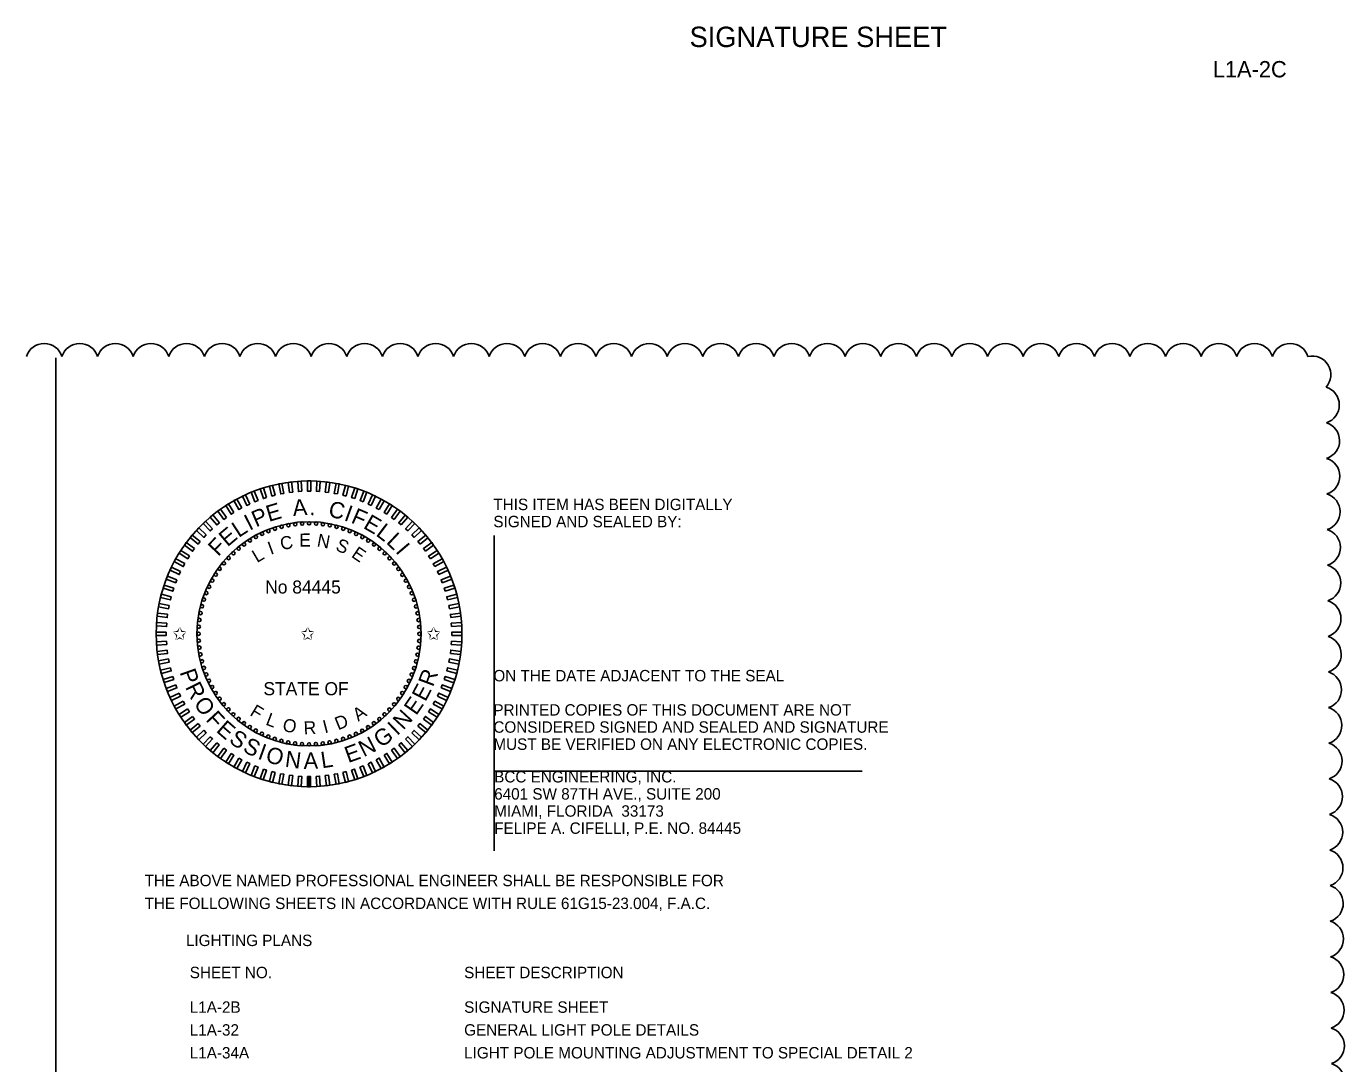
# Model space of a CAD drawing. Extents: x -811.2 to -795.1, y -2238.2 to -2204.
# Drawn here: x -803.27 to -795.18, y -2232.26 to -2225.9 of the extents above; entities that cross this region are included whole.
import ezdxf

# ---------------------------------------------------------------- set-up
doc = ezdxf.new("R2010")
doc.units = 0
for name, color, linetype in [('AdhocPoint_dp', 7, 'Continuous'), ('Cloud_dp', 7, 'Continuous'), ('PlotBorder_dp', 7, 'Continuous'), ('SheetLines_dp', 7, 'Continuous'), ('TextMinor', 7, 'Continuous'), ('TextMisc', 7, 'Continuous'), ('TextNotes', 7, 'Continuous'), ('TextShtNo', 7, 'Continuous')]:
    doc.layers.add(name, color=color, linetype=linetype)

msp = doc.modelspace()

# ---------------------------------------------------------------- linework, layer by layer
at = {"layer": 'AdhocPoint_dp'}
for p, q in [((-800.3974, -2229.0197), (-800.3974, -2230.9544)), ((-800.3974, -2230.4644), (-798.1407, -2230.4644))]:
    msp.add_line(p, q, dxfattribs=at)
at = {"layer": 'Cloud_dp'}
for centre, start, end in [((-803.1571, -2227.9569), 17.50004, 162.50004), ((-802.9388, -2227.9569), 17.5, 162.5), ((-802.7205, -2227.9569), 17.5, 162.5), ((-802.5022, -2227.9569), 17.5, 162.5), ((-802.2839, -2227.9569), 17.5, 162.5), ((-802.0655, -2227.9569), 17.5, 162.5), ((-801.8472, -2227.9569), 17.5, 162.5), ((-801.6289, -2227.9569), 17.5, 162.5), ((-801.4106, -2227.9569), 17.5, 162.5), ((-801.1922, -2227.9569), 17.5, 162.5), ((-800.9739, -2227.9569), 17.5, 162.5), ((-800.7556, -2227.9569), 17.5, 162.5), ((-800.5373, -2227.9569), 17.5, 162.5), ((-800.3189, -2227.9569), 17.5, 162.5), ((-800.1006, -2227.9569), 17.5, 162.5), ((-799.8823, -2227.9569), 17.5, 162.5), ((-799.664, -2227.9569), 17.5, 162.5), ((-799.4456, -2227.9569), 17.5, 162.5), ((-799.2273, -2227.9569), 17.5, 162.5), ((-799.009, -2227.9569), 17.5, 162.5), ((-798.7907, -2227.9569), 17.5, 162.5), ((-798.5724, -2227.9569), 17.5, 162.5), ((-798.354, -2227.9569), 17.5, 162.5), ((-798.1357, -2227.9569), 17.5, 162.5), ((-797.9174, -2227.9569), 17.5, 162.5), ((-797.6991, -2227.9569), 17.5, 162.5), ((-797.4807, -2227.9569), 17.5, 162.5), ((-797.2624, -2227.9569), 17.5, 162.5), ((-797.0441, -2227.9569), 17.5, 162.5), ((-796.8258, -2227.9569), 17.5, 162.5), ((-796.6074, -2227.9569), 17.5, 162.5), ((-796.3891, -2227.9569), 17.5, 162.5), ((-796.1708, -2227.9569), 17.5, 162.5), ((-795.9525, -2227.9569), 17.5, 162.5), ((-795.7341, -2227.9569), 17.5, 162.5), ((-795.5158, -2227.9569), 17.5, 162.5), ((-795.3807, -2228.034), 318.11161, 103.11161), ((-795.329, -2228.2198), 287.95289, 72.95289), ((-795.3273, -2228.4382), 287.95289, 72.95289), ((-795.3256, -2228.6565), 287.95289, 72.95289), ((-795.3239, -2228.8748), 287.95289, 72.95289), ((-795.3221, -2229.0931), 287.95289, 72.95289), ((-795.3204, -2229.3114), 287.95289, 72.95289), ((-795.3187, -2229.5297), 287.95289, 72.95289), ((-795.317, -2229.7481), 287.95289, 72.95289), ((-795.3152, -2229.9664), 287.95289, 72.95289), ((-795.3135, -2230.1847), 287.95289, 72.95289), ((-795.3118, -2230.403), 287.95289, 72.95289), ((-795.3101, -2230.6213), 287.95289, 72.95289), ((-795.3083, -2230.8396), 287.95289, 72.95289), ((-795.3066, -2231.058), 287.95289, 72.95289), ((-795.3049, -2231.2763), 287.95289, 72.95289), ((-795.3032, -2231.4946), 287.95289, 72.95289), ((-795.3014, -2231.7129), 287.95289, 72.95289), ((-795.2997, -2231.9312), 287.95289, 72.95289), ((-795.298, -2232.1495), 287.95289, 72.95289), ((-795.2963, -2232.3679), 287.95289, 72.95289)]:
    msp.add_arc(centre, 0.1145, start, end, dxfattribs=at)
at = {"layer": 'TextMinor'}
for radius in [0.9375, 0.6875]:
    msp.add_circle((-801.5329, -2229.6231), radius, dxfattribs=at)
at = {"layer": 'TextNotes'}
msp.add_line((-803.0858, -2237.5311), (-803.0858, -2227.9311), dxfattribs=at)
at = {"layer": 'TextShtNo'}
for p, q in [((-801.5429, -2230.5606), (-801.5431, -2230.4981)), ((-801.5329, -2230.5606), (-801.5331, -2230.4981)), ((-801.5229, -2230.5605), (-801.5231, -2230.498))]:
    msp.add_line(p, q, dxfattribs=at)
for points in [[(-801.7936, -2228.7877), (-801.8128, -2228.794), (-801.8321, -2228.7346), (-801.8129, -2228.7283)], [(-801.7407, -2228.773), (-801.7602, -2228.778), (-801.7757, -2228.7175), (-801.7562, -2228.7125)], [(-801.6869, -2228.7616), (-801.7067, -2228.7654), (-801.7184, -2228.7041), (-801.6986, -2228.7003)], [(-801.6325, -2228.7537), (-801.6525, -2228.7562), (-801.6603, -2228.6942), (-801.6403, -2228.6917)], [(-801.5777, -2228.7491), (-801.5978, -2228.7504), (-801.6018, -2228.6881), (-801.5816, -2228.6868)], [(-801.5227, -2228.748), (-801.5429, -2228.748), (-801.5429, -2228.6856), (-801.5227, -2228.6856)], [(-801.4678, -2228.7504), (-801.488, -2228.7491), (-801.484, -2228.6868), (-801.4639, -2228.6881)], [(-801.4131, -2228.7562), (-801.4332, -2228.7537), (-801.4253, -2228.6917), (-801.4053, -2228.6943)], [(-801.359, -2228.7655), (-801.3788, -2228.7617), (-801.3671, -2228.7003), (-801.3473, -2228.7041)], [(-801.3054, -2228.7781), (-801.325, -2228.773), (-801.3095, -2228.7126), (-801.2899, -2228.7176)], [(-801.2528, -2228.794), (-801.272, -2228.7878), (-801.2527, -2228.7284), (-801.2335, -2228.7346)], [(-801.9455, -2228.8514), (-801.9632, -2228.8611), (-801.9933, -2228.8064), (-801.9756, -2228.7967)], [(-801.8963, -2228.827), (-801.9145, -2228.8356), (-801.9411, -2228.7791), (-801.9229, -2228.7705)], [(-801.8456, -2228.8057), (-801.8643, -2228.8132), (-801.8873, -2228.7551), (-801.8686, -2228.7477)], [(-801.2013, -2228.8132), (-801.2201, -2228.8058), (-801.1971, -2228.7478), (-801.1783, -2228.7552)], [(-801.1511, -2228.8357), (-801.1694, -2228.8271), (-801.1428, -2228.7706), (-801.1246, -2228.7792)], [(-801.1024, -2228.8612), (-801.1201, -2228.8515), (-801.0901, -2228.7967), (-801.0724, -2228.8065)], [(-802.0828, -2228.9424), (-802.0984, -2228.9552), (-802.1382, -2228.9071), (-802.1226, -2228.8942)], [(-802.039, -2228.9092), (-802.0553, -2228.921), (-802.092, -2228.8705), (-802.0757, -2228.8587)], [(-801.9932, -2228.8788), (-802.0102, -2228.8896), (-802.0437, -2228.8369), (-802.0266, -2228.8261)], [(-801.0555, -2228.8897), (-801.0725, -2228.8789), (-801.039, -2228.8262), (-801.022, -2228.837)], [(-801.0104, -2228.9211), (-801.0267, -2228.9093), (-800.99, -2228.8588), (-800.9737, -2228.8706)], [(-800.9673, -2228.9553), (-800.9829, -2228.9425), (-800.9431, -2228.8944), (-800.9275, -2228.9072)], [(-802.1638, -2229.0166), (-802.1776, -2229.0314), (-802.2232, -2228.9886), (-802.2093, -2228.9739)], [(-802.1245, -2228.9782), (-802.1392, -2228.992), (-802.182, -2228.9465), (-802.1672, -2228.9327)], [(-800.9265, -2228.9922), (-800.9412, -2228.9784), (-800.8985, -2228.9328), (-800.8838, -2228.9467)], [(-800.8881, -2229.0315), (-800.9019, -2229.0168), (-800.8564, -2228.974), (-800.8426, -2228.9888)], [(-802.2007, -2229.0575), (-802.2135, -2229.073), (-802.2616, -2229.0332), (-802.2488, -2229.0177)], [(-800.8522, -2229.0732), (-800.8651, -2229.0576), (-800.817, -2229.0178), (-800.8041, -2229.0334)], [(-802.2663, -2229.1456), (-802.2771, -2229.1627), (-802.3298, -2229.1292), (-802.319, -2229.1122)], [(-802.2348, -2229.1005), (-802.2467, -2229.1168), (-802.2972, -2229.0801), (-802.2854, -2229.0638)], [(-800.819, -2229.117), (-800.8309, -2229.1007), (-800.7804, -2229.064), (-800.7685, -2229.0803)], [(-800.7887, -2229.1628), (-800.7995, -2229.1458), (-800.7467, -2229.1123), (-800.7359, -2229.1294)], [(-802.3203, -2229.2413), (-802.3289, -2229.2596), (-802.3854, -2229.233), (-802.3768, -2229.2147)], [(-802.2948, -2229.1926), (-802.3045, -2229.2103), (-802.3593, -2229.1802), (-802.3495, -2229.1625)], [(-800.7612, -2229.2105), (-800.7709, -2229.1928), (-800.7162, -2229.1627), (-800.7065, -2229.1804)], [(-800.7368, -2229.2597), (-800.7454, -2229.2415), (-800.6889, -2229.2149), (-800.6803, -2229.2331)], [(-802.3428, -2229.2915), (-802.3502, -2229.3103), (-802.4082, -2229.2873), (-802.4008, -2229.2685)], [(-800.7156, -2229.3104), (-800.723, -2229.2917), (-800.665, -2229.2687), (-800.6575, -2229.2874)], [(-802.3779, -2229.3956), (-802.3829, -2229.4151), (-802.4434, -2229.3996), (-802.4384, -2229.3801)], [(-802.362, -2229.343), (-802.3682, -2229.3622), (-802.4276, -2229.3429), (-802.4214, -2229.3237)], [(-800.6976, -2229.3624), (-800.7038, -2229.3432), (-800.6444, -2229.3239), (-800.6382, -2229.3431)], [(-800.6828, -2229.4153), (-800.6879, -2229.3958), (-800.6274, -2229.3802), (-800.6224, -2229.3998)], [(-802.3905, -2229.4491), (-802.3943, -2229.4689), (-802.4557, -2229.4572), (-802.4519, -2229.4374)], [(-800.6715, -2229.4691), (-800.6753, -2229.4493), (-800.6139, -2229.4376), (-800.6101, -2229.4574)], [(-802.3998, -2229.5033), (-802.4023, -2229.5233), (-802.4643, -2229.5155), (-802.4617, -2229.4955)], [(-800.6635, -2229.5235), (-800.666, -2229.5035), (-800.6041, -2229.4957), (-800.6016, -2229.5157)], [(-802.408, -2229.6129), (-802.408, -2229.6331), (-802.4704, -2229.6331), (-802.4704, -2229.6129)], [(-802.4056, -2229.558), (-802.4069, -2229.5781), (-802.4692, -2229.5742), (-802.4679, -2229.554)], [(-800.659, -2229.5783), (-800.6602, -2229.5581), (-800.5979, -2229.5542), (-800.5967, -2229.5744)], [(-800.6579, -2229.6333), (-800.6579, -2229.6131), (-800.5955, -2229.6131), (-800.5955, -2229.6333)], [(-802.4069, -2229.6679), (-802.4056, -2229.688), (-802.4679, -2229.6919), (-802.4692, -2229.6718)], [(-800.6603, -2229.6882), (-800.659, -2229.668), (-800.5967, -2229.672), (-800.5979, -2229.6921)], [(-802.4023, -2229.7226), (-802.3998, -2229.7427), (-802.4617, -2229.7505), (-802.4643, -2229.7305)], [(-802.3944, -2229.777), (-802.3906, -2229.7969), (-802.4519, -2229.8086), (-802.4557, -2229.7887)], [(-800.6753, -2229.797), (-800.6715, -2229.7772), (-800.6102, -2229.7889), (-800.614, -2229.8087)], [(-800.6661, -2229.7428), (-800.6635, -2229.7228), (-800.6016, -2229.7306), (-800.6041, -2229.7507)], [(-802.383, -2229.8308), (-802.378, -2229.8504), (-802.4385, -2229.8659), (-802.4435, -2229.8463)], [(-800.6879, -2229.8506), (-800.6829, -2229.831), (-800.6224, -2229.8465), (-800.6274, -2229.8661)], [(-802.3683, -2229.8838), (-802.362, -2229.903), (-802.4214, -2229.9223), (-802.4277, -2229.9031)], [(-802.3503, -2229.9357), (-802.3428, -2229.9545), (-802.4009, -2229.9775), (-802.4083, -2229.9587)], [(-800.7231, -2229.9547), (-800.7157, -2229.9359), (-800.6576, -2229.9589), (-800.665, -2229.9776)], [(-800.7039, -2229.9032), (-800.6976, -2229.884), (-800.6382, -2229.9033), (-800.6445, -2229.9225)], [(-802.329, -2229.9864), (-802.3204, -2230.0047), (-802.3769, -2230.0313), (-802.3855, -2230.013)], [(-800.7455, -2230.0049), (-800.7369, -2229.9866), (-800.6804, -2230.0132), (-800.689, -2230.0314)], [(-802.3046, -2230.0357), (-802.2949, -2230.0534), (-802.3496, -2230.0835), (-802.3593, -2230.0658)], [(-802.2772, -2230.0833), (-802.2664, -2230.1004), (-802.3191, -2230.1338), (-802.3299, -2230.1168)], [(-800.7996, -2230.1005), (-800.7888, -2230.0835), (-800.736, -2230.117), (-800.7468, -2230.134)], [(-800.771, -2230.0535), (-800.7613, -2230.0359), (-800.7066, -2230.0659), (-800.7163, -2230.0836)], [(-802.2468, -2230.1292), (-802.235, -2230.1455), (-802.2855, -2230.1822), (-802.2973, -2230.1659)], [(-802.2136, -2230.173), (-802.2008, -2230.1885), (-802.2489, -2230.2283), (-802.2617, -2230.2128)], [(-800.8652, -2230.1887), (-800.8523, -2230.1731), (-800.8042, -2230.2129), (-800.8171, -2230.2285)], [(-800.831, -2230.1456), (-800.8191, -2230.1293), (-800.7686, -2230.166), (-800.7805, -2230.1823)], [(-802.1778, -2230.2146), (-802.1639, -2230.2294), (-802.2095, -2230.2721), (-802.2233, -2230.2574)], [(-802.1393, -2230.254), (-802.1246, -2230.2678), (-802.1674, -2230.3133), (-802.1821, -2230.2995)], [(-800.9413, -2230.2679), (-800.9266, -2230.2541), (-800.8839, -2230.2996), (-800.8986, -2230.3134)], [(-800.902, -2230.2295), (-800.8882, -2230.2148), (-800.8427, -2230.2575), (-800.8565, -2230.2722)], [(-802.0985, -2230.2908), (-802.083, -2230.3037), (-802.1228, -2230.3518), (-802.1383, -2230.3389)], [(-802.0555, -2230.325), (-802.0392, -2230.3369), (-802.0759, -2230.3874), (-802.0922, -2230.3755)], [(-801.0268, -2230.337), (-801.0105, -2230.3251), (-800.9738, -2230.3756), (-800.9901, -2230.3875)], [(-800.983, -2230.3038), (-800.9675, -2230.2909), (-800.9277, -2230.339), (-800.9432, -2230.3519)], [(-802.0104, -2230.3564), (-801.9933, -2230.3672), (-802.0268, -2230.42), (-802.0438, -2230.4091)], [(-801.9634, -2230.385), (-801.9457, -2230.3947), (-801.9758, -2230.4494), (-801.9935, -2230.4397)], [(-801.9147, -2230.4105), (-801.8964, -2230.4191), (-801.923, -2230.4756), (-801.9413, -2230.467)], [(-801.8645, -2230.4329), (-801.8457, -2230.4403), (-801.8687, -2230.4984), (-801.8875, -2230.491)], [(-801.2203, -2230.4404), (-801.2015, -2230.433), (-801.1785, -2230.491), (-801.1973, -2230.4985)], [(-801.1696, -2230.4192), (-801.1513, -2230.4106), (-801.1247, -2230.4671), (-801.143, -2230.4757)], [(-801.1203, -2230.3948), (-801.1026, -2230.3851), (-801.0725, -2230.4398), (-801.0902, -2230.4495)], [(-801.0727, -2230.3673), (-801.0556, -2230.3565), (-801.0222, -2230.4092), (-801.0392, -2230.4201)], [(-801.813, -2230.4521), (-801.7938, -2230.4584), (-801.8131, -2230.5178), (-801.8323, -2230.5115)], [(-801.7604, -2230.4681), (-801.7408, -2230.4731), (-801.7564, -2230.5336), (-801.7759, -2230.5286)], [(-801.7069, -2230.4807), (-801.6871, -2230.4845), (-801.6988, -2230.5458), (-801.7186, -2230.542)], [(-801.6527, -2230.4899), (-801.6327, -2230.4925), (-801.6405, -2230.5544), (-801.6605, -2230.5519)], [(-801.598, -2230.4957), (-801.5779, -2230.497), (-801.5818, -2230.5593), (-801.602, -2230.5581)], [(-801.5431, -2230.4981), (-801.5229, -2230.4981), (-801.5229, -2230.5605), (-801.5431, -2230.5605)], [(-801.4881, -2230.497), (-801.468, -2230.4957), (-801.4641, -2230.5581), (-801.4842, -2230.5593)], [(-801.4334, -2230.4925), (-801.4133, -2230.4899), (-801.4055, -2230.5519), (-801.4255, -2230.5544)], [(-801.379, -2230.4845), (-801.3591, -2230.4807), (-801.3474, -2230.5421), (-801.3673, -2230.5458)], [(-801.3252, -2230.4731), (-801.3056, -2230.4681), (-801.2901, -2230.5286), (-801.3096, -2230.5336)], [(-801.2722, -2230.4584), (-801.253, -2230.4522), (-801.2337, -2230.5116), (-801.2529, -2230.5178)]]:
    msp.add_lwpolyline(points, close=True, dxfattribs=at)
for centre in [(-801.7417, -2228.9786), (-801.7009, -2228.9667), (-801.6593, -2228.9575), (-801.6173, -2228.9509), (-801.5749, -2228.9469), (-801.5324, -2228.9456), (-801.4898, -2228.947), (-801.4475, -2228.951), (-801.4054, -2228.9577), (-801.3639, -2228.967), (-801.323, -2228.9789), (-801.8955, -2229.0508), (-801.8588, -2229.0291), (-801.8209, -2229.0098), (-801.7818, -2228.993), (-801.283, -2228.9934), (-801.244, -2229.0103), (-801.2061, -2229.0297), (-801.1694, -2229.0514), (-801.9963, -2229.1288), (-801.9643, -2229.1007), (-801.9307, -2229.0747), (-801.1343, -2229.0753), (-801.1007, -2229.1014), (-801.0688, -2229.1296), (-802.0807, -2229.2244), (-802.0546, -2229.1908), (-802.0264, -2229.1589), (-801.0387, -2229.1597), (-801.0106, -2229.1917), (-800.9845, -2229.2253), (-802.1263, -2229.2962), (-802.1046, -2229.2596), (-800.9606, -2229.2605), (-800.939, -2229.2972), (-802.1626, -2229.3732), (-802.1457, -2229.3341), (-800.9197, -2229.3351), (-800.9028, -2229.3742), (-802.189, -2229.454), (-802.1771, -2229.4132), (-800.8884, -2229.4143), (-800.8766, -2229.4551), (-802.205, -2229.5376), (-802.1983, -2229.4956), (-800.8673, -2229.4967), (-800.8607, -2229.5387), (-802.2104, -2229.6225), (-802.209, -2229.58), (-800.8568, -2229.5811), (-800.8555, -2229.6236), (-802.2091, -2229.665), (-802.2051, -2229.7074), (-800.8609, -2229.7085), (-800.8568, -2229.6662), (-802.1985, -2229.7495), (-802.1892, -2229.791), (-800.8769, -2229.7921), (-800.8676, -2229.7506), (-802.1774, -2229.8319), (-802.163, -2229.8719), (-800.9032, -2229.873), (-800.8888, -2229.833), (-802.1462, -2229.911), (-802.1269, -2229.949), (-800.9395, -2229.9499), (-800.9202, -2229.912), (-802.1052, -2229.9856), (-802.0813, -2230.0208), (-800.9852, -2230.0217), (-800.9612, -2229.9866), (-802.0553, -2230.0545), (-802.0272, -2230.0864), (-801.9971, -2230.1165), (-801.0696, -2230.1173), (-801.0395, -2230.0872), (-801.0113, -2230.0553), (-801.9652, -2230.1447), (-801.9316, -2230.1708), (-801.8964, -2230.1948), (-801.1704, -2230.1954), (-801.1352, -2230.1715), (-801.1015, -2230.1454), (-801.8598, -2230.2165), (-801.8219, -2230.2358), (-801.7828, -2230.2528), (-801.7428, -2230.2672), (-801.7019, -2230.2791), (-801.365, -2230.2794), (-801.3241, -2230.2676), (-801.2841, -2230.2532), (-801.245, -2230.2363), (-801.207, -2230.217), (-801.6604, -2230.2884), (-801.6184, -2230.2951), (-801.576, -2230.2992), (-801.5329, -2230.3006), (-801.4909, -2230.2992), (-801.4486, -2230.2953), (-801.4065, -2230.2886)]:
    msp.add_circle(centre, 0.01, dxfattribs=at)

# ---------------------------------------------------------------- texts
at = {"layer": 'PlotBorder_dp'}
for s, height, p in [('       SIGNATURE SHEET         ', 0.125, (-799.5241, -2226.0251)), ('THIS ITEM HAS BEEN DIGITALLY', 0.07, (-800.4024, -2228.8645)), ('SIGNED AND SEALED BY:', 0.07, (-800.4024, -2228.9695)), ('ON THE DATE ADJACENT TO THE SEAL', 0.07, (-800.4024, -2229.9145)), ('PRINTED COPIES OF THIS DOCUMENT ARE NOT ', 0.07, (-800.4024, -2230.1245)), ('CONSIDERED SIGNED AND SEALED AND SIGNATURE ', 0.07, (-800.4024, -2230.2295)), ('MUST BE VERIFIED ON ANY ELECTRONIC COPIES.', 0.07, (-800.4024, -2230.3345)), ('BCC ENGINEERING, INC.', 0.07, (-800.3974, -2230.5344)), ('6401 SW 87TH AVE., SUITE 200', 0.07, (-800.3974, -2230.6394)), ('MIAMI, FLORIDA  33173', 0.07, (-800.3974, -2230.7444)), ('FELIPE A. CIFELLI, P.E. NO. 84445', 0.07, (-800.3974, -2230.8494)), ('THE ABOVE NAMED PROFESSIONAL ENGINEER SHALL BE RESPONSIBLE FOR ', 0.07, (-802.5415, -2231.1705)), ('THE FOLLOWING SHEETS IN ACCORDANCE WITH RULE 61G15-23.004, F.A.C.', 0.07, (-802.5415, -2231.3105)), ('LIGHTING PLANS', 0.07, (-802.2878, -2231.5376))]:
    msp.add_text(s, height=height, dxfattribs=at).set_placement(p)
at = {"layer": 'SheetLines_dp'}
msp.add_text('L1A-2C', height=0.1, dxfattribs=at).set_placement((-795.9904, -2226.2108))
at = {"layer": 'TextMisc'}
for s, p in [('SHEET NO.', (-802.2643, -2231.7345)), ('SHEET DESCRIPTION', (-800.5815, -2231.7345)), ('L1A-2B', (-802.2643, -2231.9467)), ('SIGNATURE SHEET', (-800.5815, -2231.9467)), ('L1A-32', (-802.2643, -2232.0867)), ('GENERAL LIGHT POLE DETAILS', (-800.5815, -2232.0867)), ('L1A-34A', (-802.2643, -2232.2267)), ('LIGHT POLE MOUNTING ADJUSTMENT TO SPECIAL DETAIL 2', (-800.5815, -2232.2267))]:
    msp.add_text(s, height=0.07, dxfattribs=at).set_placement(p)
at = {"layer": 'TextShtNo'}
for s, height, rotation, p in [('E', 0.1, 16.54261, (-801.7793, -2228.9373)), ('A', 0.1, 4.42103, (-801.6298, -2228.9009)), ('C', 0.1, 347.7999, (-801.4192, -2228.9033)), ('I', 0.1, 26.81606, (-801.8977, -2228.9923)), ('P', 0.1, 23.28287, (-801.8581, -2228.971)), ('.', 0.1, 356.65403, (-801.5313, -2228.8944)), ('I', 0.1, 340.0631, (-801.3234, -2228.9252)), ('F', 0.1, 336.52991, (-801.2807, -2228.9395)), ('E', 0.1, 330.07956, (-801.2055, -2228.9721)), ('E', 0.1, 40.12142, (-802.033, -2229.0932)), ('L', 0.1, 33.07918, (-801.9643, -2229.0358)), ('L', 0.1, 323.03732, (-801.1282, -2229.0172)), ('F', 0.1, 46.57177, (-802.0894, -2229.1527)), ('I', 0.08, 20.01168, (-801.7686, -2229.139)), ('C', 0.08, 12.20255, (-801.7007, -2229.1115)), ('E', 0.08, 0.41861, (-801.5926, -2229.088)), ('N', 0.08, 349.29143, (-801.4883, -2229.0865)), ('S', 0.08, 337.02207, (-801.3753, -2229.1083)), ('L', 0.1, 316.7742, (-801.0645, -2229.0649)), ('L', 0.08, 30.40215, (-801.8521, -2229.1895)), ('E', 0.08, 325.86633, (-801.2786, -2229.1485)), ('I', 0.1, 310.51108, (-801.0064, -2229.1194)), ('P', 0.1, 289.40551, (-802.3276, -2229.8577)), ('R', 0.1, 69.5134, (-800.7727, -2229.9528)), ('R', 0.1, 296.14576, (-802.2946, -2229.9493)), ('E', 0.1, 62.47116, (-800.8189, -2230.0435)), ('O', 0.1, 303.96711, (-802.2431, -2230.0499)), ('E', 0.1, 55.42892, (-800.8758, -2230.1279)), ('F', 0.1, 312.62798, (-802.1707, -2230.152)), ('F', 0.08, 328.72408, (-801.901, -2230.1197)), ('L', 0.08, 339.29159, (-801.8037, -2230.1787)), ('A', 0.08, 34.49917, (-801.2311, -2230.1625)), ('N', 0.1, 47.17876, (-800.9551, -2230.2169)), ('E', 0.1, 319.07833, (-802.1073, -2230.2203)), ('O', 0.08, 349.68206, (-801.699, -2230.2185)), ('R', 0.08, 2.33977, (-801.5645, -2230.2404)), ('I', 0.08, 14.20366, (-801.4369, -2230.2337)), ('D', 0.08, 22.01279, (-801.3548, -2230.215)), ('I', 0.1, 43.64556, (-800.9928, -2230.2514)), ('S', 0.1, 326.12056, (-802.0297, -2230.2862)), ('S', 0.1, 333.193, (-801.9443, -2230.3423)), ('N', 0.1, 26.86136, (-801.1972, -2230.3806)), ('G', 0.1, 35.11153, (-801.092, -2230.3246)), ('I', 0.1, 340.26543, (-801.8526, -2230.3875)), ('O', 0.1, 343.79863, (-801.8049, -2230.4058)), ('N', 0.1, 352.45949, (-801.6839, -2230.4378)), ('A', 0.1, 0.70966, (-801.5655, -2230.451)), ('L', 0.1, 8.47665, (-801.4533, -2230.4478)), ('E', 0.1, 19.81912, (-801.2926, -2230.4161))]:
    msp.add_text(s, height=height, rotation=rotation, dxfattribs=at).set_placement(p)
for s, p in [('No 84445', (-801.8019, -2229.3758)), ('✩', (-802.3679, -2229.661)), ('✩', (-801.5832, -2229.661)), ('✩', (-800.8113, -2229.661)), ('STATE OF', (-801.8126, -2229.9993))]:
    msp.add_text(s, height=0.08, dxfattribs=at).set_placement(p)

doc.saveas('drawing.dxf')
